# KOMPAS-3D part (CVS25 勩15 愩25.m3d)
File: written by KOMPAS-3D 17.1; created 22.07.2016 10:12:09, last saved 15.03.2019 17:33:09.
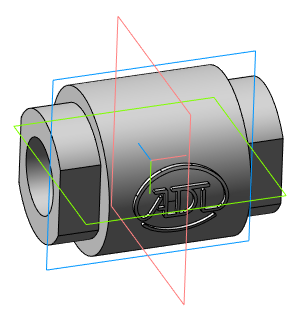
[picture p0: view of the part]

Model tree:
1. Операция без истории:2  (labels: Сталь 20  ГОСТ 1050-88)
